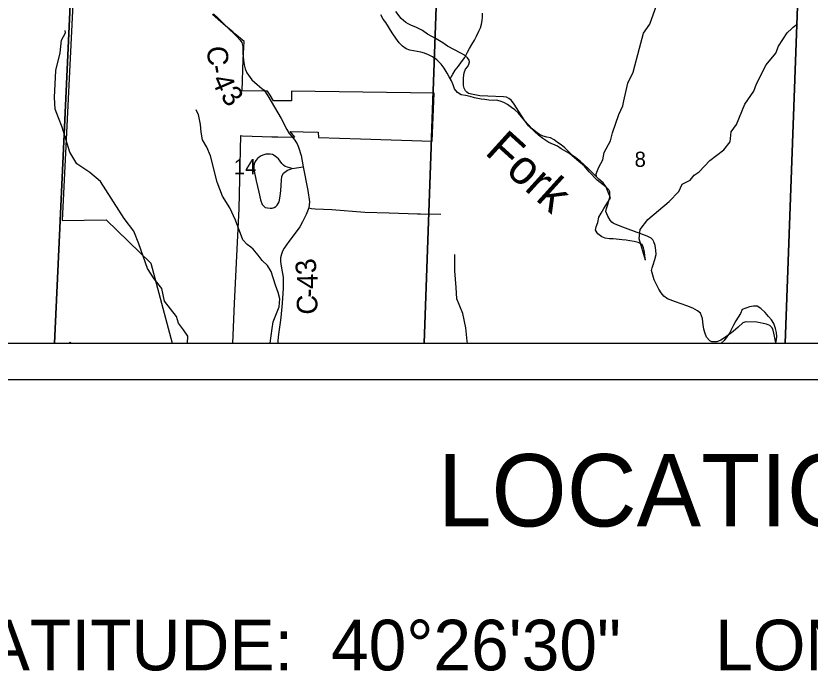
# Model space of a CAD drawing. Extents: x 0 to 34, y 0 to 22.
# Drawn here: x 3.261 to 5.456, y 13.194 to 15.005 of the extents above; entities that cross this region are included whole.
import ezdxf

# ---------------------------------------------------------------- set-up
doc = ezdxf.new("R2010")
doc.units = 0
for name, color, linetype in [('Default', 7, 'Continuous'), ('GM_X_County_Road', 7, 'Continuous'), ('GM_X_County_Road_Text', 7, 'Continuous'), ('GM_X_Minor_River', 7, 'Continuous'), ('GM_X_Minor_River_Text', 7, 'Continuous'), ('GM_X_Section_Text', 7, 'Continuous'), ('GM_X_Township_Road', 7, 'Continuous'), ('SH_Cut_Line', 7, 'Continuous'), ('SH_Data', 7, 'Continuous'), ('SH_Text', 7, 'Continuous')]:
    doc.layers.add(name, color=color, linetype=linetype)

msp = doc.modelspace()

# ---------------------------------------------------------------- linework, layer by layer
at = {"layer": 'Default'}
for p, q in [((3.3681, 14.1), (3.4148, 15.1232)), ((3.4148, 15.1232), (3.3681, 14.1)), ((3.4223, 15.1228), (3.389, 14.4392)), ((4.3897, 14.1), (4.4256, 15.1132)), ((4.4256, 15.1132), (4.3897, 14.1)), ((5.4229, 15.0756), (5.3878, 14.1)), ((5.3878, 14.1), (5.4229, 15.0756)), ((3.8279, 14.9887), (3.8044, 15.0089)), ((3.8459, 14.9733), (3.8279, 14.9887)), ((3.8516, 14.9685), (3.8459, 14.9733)), ((3.8606, 14.9607), (3.8516, 14.9685)), ((3.8664, 14.9558), (3.8606, 14.9607)), ((3.8917, 14.9341), (3.8664, 14.9558)), ((3.8897, 14.8843), (3.8917, 14.9341)), ((3.8867, 14.7981), (3.8897, 14.8843)), ((3.9476, 14.7973), (3.8867, 14.7981)), ((3.957, 14.7973), (3.9476, 14.7973)), ((3.9636, 14.7854), (3.957, 14.7973)), ((4.4177, 14.7917), (4.023, 14.7972)), ((4.023, 14.7972), (4.023, 14.77)), ((3.9727, 14.7699), (3.9636, 14.7854)), ((4.412, 14.6591), (4.4177, 14.7917)), ((4.023, 14.77), (3.9727, 14.7699)), ((3.878, 14.4728), (3.8829, 14.674)), ((3.8829, 14.674), (3.8873, 14.6738)), ((3.8873, 14.6738), (3.9684, 14.671)), ((3.9684, 14.671), (3.985, 14.6707)), ((3.985, 14.6707), (4.0317, 14.6698)), ((4.0317, 14.6698), (4.0192, 14.6857)), ((4.0192, 14.6857), (4.0552, 14.6845)), ((4.0552, 14.6845), (4.0969, 14.6836)), ((4.0969, 14.6836), (4.0972, 14.6685)), ((4.0972, 14.6685), (4.214, 14.6654)), ((4.214, 14.6654), (4.412, 14.6591)), ((3.8654, 14.21), (3.878, 14.4728)), ((3.389, 14.4392), (3.5109, 14.4412)), ((3.5109, 14.4412), (3.634, 14.3213)), ((3.634, 14.3213), (3.6931, 14.1)), ((3.8609, 14.1), (3.8654, 14.21)), ((2.1, 14.1), (6.7017, 14.1)), ((3.167, 14.1), (3.3681, 14.1)), ((3.3681, 14.1), (4.3897, 14.1)), ((3.4115, 14.1029), (3.4086, 14.1)), ((3.4086, 14.1), (3.4147, 14.1)), ((3.6931, 14.1), (3.8609, 14.1)), ((4.3897, 14.1), (5.3878, 14.1)), ((5.3878, 14.1), (6.3909, 14.1))]:
    msp.add_line(p, q, dxfattribs=at)
msp.add_arc((3.4499, 14.1421), 0.0549, 225.573, 230.0477, dxfattribs=at)
at = {"layer": 'GM_X_County_Road'}
for p, q in [((3.8069, 15.0107), (3.8205, 14.9991)), ((3.8205, 14.9991), (3.8434, 14.9758)), ((3.8434, 14.9758), (3.8711, 14.9492)), ((3.8711, 14.9492), (3.881, 14.9376)), ((3.881, 14.9376), (3.8856, 14.9312)), ((3.8856, 14.9312), (3.8877, 14.9242)), ((3.8877, 14.9242), (3.888, 14.9232)), ((3.888, 14.9232), (3.8888, 14.9019)), ((3.8888, 14.9019), (3.8901, 14.883)), ((3.8901, 14.883), (3.892, 14.8695)), ((3.892, 14.8695), (3.8949, 14.859)), ((3.8949, 14.859), (3.8993, 14.8473)), ((3.8993, 14.8473), (3.9134, 14.8281)), ((3.9134, 14.8281), (3.9276, 14.815)), ((3.9276, 14.815), (3.9413, 14.8042)), ((3.9413, 14.8042), (3.947, 14.7997)), ((3.947, 14.7997), (3.9575, 14.7844)), ((3.9575, 14.7844), (3.9762, 14.7527)), ((3.9762, 14.7527), (3.9942, 14.7211)), ((3.9942, 14.7211), (4.0103, 14.6913)), ((4.0103, 14.6913), (4.0168, 14.6798)), ((4.0168, 14.6798), (4.0186, 14.6776)), ((4.0186, 14.6776), (4.0271, 14.6671)), ((4.0271, 14.6671), (4.0324, 14.6612)), ((4.0324, 14.6612), (4.0352, 14.6571)), ((4.0352, 14.6571), (4.0386, 14.6514)), ((4.0386, 14.6514), (4.0424, 14.6423)), ((4.0424, 14.6423), (4.0495, 14.6188)), ((4.0495, 14.6188), (4.0555, 14.5876)), ((4.0555, 14.5876), (4.0678, 14.522)), ((4.0678, 14.522), (4.0728, 14.4907)), ((4.0728, 14.4907), (4.0712, 14.4745)), ((4.0712, 14.4745), (4.0635, 14.4563)), ((4.0635, 14.4563), (4.0529, 14.4353)), ((4.0529, 14.4353), (4.0455, 14.4222)), ((4.0356, 14.4077), (4.0156, 14.3812)), ((4.0455, 14.4222), (4.0356, 14.4077)), ((4.0156, 14.3812), (4.0029, 14.363)), ((4.0029, 14.363), (3.9984, 14.3544)), ((3.9929, 14.3361), (3.9928, 14.3258)), ((3.9949, 14.3463), (3.9929, 14.3361)), ((3.9984, 14.3544), (3.9949, 14.3463)), ((3.9928, 14.3258), (3.9945, 14.3132)), ((3.9945, 14.3132), (3.9995, 14.2829)), ((3.9995, 14.2829), (4.0001, 14.252)), ((4.0001, 14.252), (3.9968, 14.2106)), ((3.9968, 14.2106), (3.9933, 14.1709)), ((3.9933, 14.1709), (3.9916, 14.1579)), ((3.9916, 14.1579), (3.9872, 14.125)), ((3.9872, 14.125), (3.9849, 14.1078)), ((3.9849, 14.1078), (3.9847, 14.1))]:
    msp.add_line(p, q, dxfattribs=at)
at = {"layer": 'GM_X_Minor_River'}
for p, q in [((5.0129, 14.9819), (5.0323, 15.0369)), ((4.2766, 14.996), (4.2698, 15.008)), ((4.2838, 14.9863), (4.2766, 14.996)), ((4.5501, 14.9919), (4.5509, 15.0019)), ((4.5509, 15.0019), (4.5506, 15.0121)), ((4.2913, 14.9748), (4.2838, 14.9863)), ((4.297, 14.9651), (4.2913, 14.9748)), ((4.5407, 14.9624), (4.545, 14.9724)), ((4.545, 14.9724), (4.5477, 14.982)), ((4.5477, 14.982), (4.5501, 14.9919)), ((4.996, 14.9573), (5.0129, 14.9819)), ((5.4062, 14.9697), (5.4096, 14.9739)), ((5.4096, 14.9739), (5.4211, 14.9832)), ((3.3875, 14.9379), (3.3978, 14.9582)), ((3.3978, 14.9582), (3.3976, 14.9647)), ((4.3026, 14.955), (4.297, 14.9651)), ((4.311, 14.9431), (4.3026, 14.955)), ((4.5343, 14.9485), (4.5407, 14.9624)), ((4.9846, 14.916), (4.996, 14.9573)), ((5.3686, 14.9212), (5.3929, 14.9577)), ((5.3929, 14.9577), (5.4062, 14.9697)), ((3.3836, 14.9029), (3.3875, 14.9379)), ((4.3201, 14.9304), (4.311, 14.9431)), ((4.3299, 14.9212), (4.3201, 14.9304)), ((4.521, 14.926), (4.5286, 14.938)), ((4.5286, 14.938), (4.5343, 14.9485)), ((4.34, 14.9139), (4.3299, 14.9212)), ((4.35, 14.9104), (4.34, 14.9139)), ((4.3603, 14.9085), (4.35, 14.9104)), ((4.3707, 14.9061), (4.3603, 14.9085)), ((4.3802, 14.9049), (4.3707, 14.9061)), ((4.5091, 14.9043), (4.5149, 14.9152)), ((4.5149, 14.9152), (4.521, 14.926)), ((4.9673, 14.8496), (4.9846, 14.916)), ((5.3617, 14.9024), (5.3686, 14.9212)), ((3.3713, 14.854), (3.3836, 14.9029)), ((4.3902, 14.9018), (4.3802, 14.9049)), ((4.4017, 14.8972), (4.3902, 14.9018)), ((4.4126, 14.8915), (4.4017, 14.8972)), ((4.4242, 14.8831), (4.4126, 14.8915)), ((4.4928, 14.8776), (4.5016, 14.89)), ((4.5016, 14.89), (4.5091, 14.9043)), ((5.3351, 14.8701), (5.3617, 14.9024)), ((4.4364, 14.8713), (4.4242, 14.8831)), ((4.4447, 14.8601), (4.4364, 14.8713)), ((4.4749, 14.855), (4.4841, 14.8663)), ((4.4841, 14.8663), (4.4928, 14.8776)), ((5.308, 14.8176), (5.3351, 14.8701)), ((3.3681, 14.7795), (3.3713, 14.854)), ((4.4531, 14.8467), (4.4447, 14.8601)), ((4.4584, 14.8366), (4.4531, 14.8467)), ((4.4615, 14.8312), (4.4688, 14.8438)), ((4.4688, 14.8438), (4.4749, 14.855)), ((4.9527, 14.8186), (4.9673, 14.8496)), ((4.4648, 14.8254), (4.4584, 14.8366)), ((4.4701, 14.8141), (4.4648, 14.8254)), ((4.9414, 14.7705), (4.9527, 14.8186)), ((4.4735, 14.8036), (4.4701, 14.8141)), ((4.4818, 14.7936), (4.4735, 14.8036)), ((5.2758, 14.7612), (5.3004, 14.7973)), ((5.3004, 14.7973), (5.308, 14.8176)), ((3.3694, 14.7472), (3.3681, 14.7795)), ((4.4923, 14.7871), (4.4818, 14.7936)), ((4.5037, 14.7851), (4.4923, 14.7871)), ((4.5171, 14.7821), (4.5037, 14.7851)), ((4.5286, 14.7787), (4.5171, 14.7821)), ((4.5474, 14.7751), (4.5286, 14.7787)), ((4.5577, 14.7735), (4.5474, 14.7751)), ((4.5684, 14.7716), (4.5577, 14.7735)), ((4.5802, 14.7715), (4.5684, 14.7716)), ((4.5897, 14.7718), (4.5802, 14.7715)), ((4.6, 14.7691), (4.5897, 14.7718)), ((4.61, 14.7652), (4.6, 14.7691)), ((4.6197, 14.7602), (4.61, 14.7652)), ((4.6306, 14.7522), (4.6197, 14.7602)), ((4.9281, 14.7323), (4.9387, 14.7564)), ((4.9387, 14.7564), (4.9414, 14.7705)), ((5.253, 14.7049), (5.2758, 14.7612)), ((3.3785, 14.7234), (3.3694, 14.7472)), ((3.7611, 14.7407), (3.7591, 14.7452)), ((3.7658, 14.7324), (3.7611, 14.7407)), ((3.7712, 14.7044), (3.7658, 14.7324)), ((4.6403, 14.7453), (4.6306, 14.7522)), ((4.6505, 14.7365), (4.6403, 14.7453)), ((4.6588, 14.7261), (4.6505, 14.7365)), ((4.9098, 14.6814), (4.9281, 14.7323)), ((3.3888, 14.6977), (3.3785, 14.7234)), ((4.6679, 14.7149), (4.6588, 14.7261)), ((4.6777, 14.7038), (4.6679, 14.7149)), ((3.4101, 14.6282), (3.3888, 14.6977)), ((3.7735, 14.6835), (3.7712, 14.7044)), ((4.6883, 14.6924), (4.6777, 14.7038)), ((4.6981, 14.6847), (4.6883, 14.6924)), ((5.2386, 14.6849), (5.253, 14.7049)), ((3.7769, 14.6623), (3.7735, 14.6835)), ((4.7082, 14.6774), (4.6981, 14.6847)), ((4.7182, 14.6724), (4.7082, 14.6774)), ((4.7282, 14.6701), (4.7182, 14.6724)), ((4.7389, 14.6677), (4.7282, 14.6701)), ((4.7486, 14.6627), (4.7389, 14.6677)), ((4.9049, 14.66), (4.9098, 14.6814)), ((5.2357, 14.6571), (5.2386, 14.6849)), ((3.789, 14.6423), (3.7769, 14.6623)), ((4.7583, 14.6554), (4.7486, 14.6627)), ((4.768, 14.6489), (4.7583, 14.6554)), ((4.7786, 14.6401), (4.768, 14.6489)), ((4.8869, 14.6274), (4.9049, 14.66)), ((5.2183, 14.6348), (5.2357, 14.6571)), ((3.4292, 14.5958), (3.4101, 14.6282)), ((3.7992, 14.6182), (3.789, 14.6423)), ((4.7899, 14.629), (4.7786, 14.6401)), ((4.7994, 14.6194), (4.7899, 14.629)), ((4.8835, 14.6069), (4.8869, 14.6274)), ((5.1791, 14.6053), (5.2183, 14.6348)), ((3.8171, 14.5451), (3.7992, 14.6182)), ((4.8091, 14.6129), (4.7994, 14.6194)), ((4.8212, 14.6034), (4.8091, 14.6129)), ((4.8321, 14.5931), (4.8212, 14.6034)), ((4.8725, 14.5869), (4.8835, 14.6069)), ((5.1498, 14.5744), (5.1791, 14.6053)), ((3.4655, 14.5717), (3.4292, 14.5958)), ((4.8427, 14.5827), (4.8321, 14.5931)), ((4.8623, 14.564), (4.8427, 14.5827)), ((4.8653, 14.5682), (4.8725, 14.5869)), ((3.4947, 14.5471), (3.4655, 14.5717)), ((4.8725, 14.554), (4.8623, 14.564)), ((4.866, 14.5603), (4.8653, 14.5682)), ((5.1245, 14.5511), (5.1356, 14.5646)), ((5.1356, 14.5646), (5.1498, 14.5744)), ((3.56, 14.4448), (3.4947, 14.5471)), ((3.8318, 14.5069), (3.8171, 14.5451)), ((4.8842, 14.5433), (4.8725, 14.554)), ((4.8914, 14.5333), (4.8842, 14.5433)), ((4.8959, 14.5228), (4.8914, 14.5333)), ((5.0933, 14.5195), (5.1028, 14.5394)), ((5.1028, 14.5394), (5.1245, 14.5511)), ((4.9004, 14.513), (4.8959, 14.5228)), ((4.9042, 14.5025), (4.9004, 14.513)), ((5.067, 14.492), (5.0933, 14.5195)), ((3.8524, 14.4742), (3.8318, 14.5069)), ((4.8926, 14.4828), (4.8991, 14.4925)), ((4.8991, 14.4925), (4.9042, 14.5025)), ((5.0074, 14.442), (5.067, 14.492)), ((3.8678, 14.4402), (3.8524, 14.4742)), ((4.8785, 14.4595), (4.8861, 14.4727)), ((4.8861, 14.4727), (4.8926, 14.4828)), ((4.8698, 14.4341), (4.8728, 14.4487)), ((4.8728, 14.4487), (4.8785, 14.4595)), ((3.5867, 14.4102), (3.56, 14.4448)), ((3.8888, 14.3859), (3.8678, 14.4402)), ((4.8652, 14.4222), (4.8698, 14.4341)), ((4.9867, 14.4147), (5.0074, 14.442)), ((3.6009, 14.3747), (3.5867, 14.4102)), ((4.8629, 14.4123), (4.8652, 14.4222)), ((4.8693, 14.4026), (4.8629, 14.4123)), ((4.8805, 14.3946), (4.8693, 14.4026)), ((4.9841, 14.3892), (4.9867, 14.4147)), ((3.9, 14.3727), (3.8888, 14.3859)), ((4.8902, 14.3907), (4.8805, 14.3946)), ((4.902, 14.3891), (4.8902, 14.3907)), ((4.9119, 14.3883), (4.902, 14.3891)), ((4.9371, 14.3861), (4.9119, 14.3883)), ((4.9478, 14.3849), (4.9371, 14.3861)), ((4.9581, 14.3833), (4.9478, 14.3849)), ((4.9703, 14.3814), (4.9581, 14.3833)), ((4.9814, 14.3783), (4.9703, 14.3814)), ((5.0012, 14.3299), (4.9841, 14.3892)), ((3.6252, 14.3071), (3.6009, 14.3747)), ((3.9107, 14.3657), (3.9, 14.3727)), ((3.9172, 14.3605), (3.9107, 14.3657)), ((3.9307, 14.344), (3.9172, 14.3605)), ((4.9926, 14.3733), (4.9814, 14.3783)), ((4.9956, 14.3635), (4.9926, 14.3733)), ((4.9982, 14.3526), (4.9956, 14.3635)), ((3.942, 14.3289), (3.9307, 14.344)), ((4.4746, 14.3284), (4.4743, 14.3451)), ((4.9997, 14.3416), (4.9982, 14.3526)), ((5.0012, 14.3299), (4.9997, 14.3416)), ((3.9566, 14.3151), (3.942, 14.3289)), ((3.9667, 14.2989), (3.9566, 14.3151)), ((4.4743, 14.2999), (4.4746, 14.3284)), ((3.6435, 14.2785), (3.6252, 14.3071)), ((3.9791, 14.2604), (3.9667, 14.2989)), ((4.4778, 14.254), (4.4743, 14.2999)), ((3.6647, 14.2515), (3.6435, 14.2785)), ((3.6722, 14.2166), (3.6647, 14.2515)), ((3.9862, 14.2403), (3.9791, 14.2604)), ((4.4802, 14.2229), (4.4778, 14.254)), ((3.9907, 14.2229), (3.9862, 14.2403)), ((3.7054, 14.1739), (3.6722, 14.2166)), ((3.9892, 14.2009), (3.9907, 14.2229)), ((4.4961, 14.1824), (4.4802, 14.2229)), ((3.9718, 14.1595), (3.9892, 14.2009)), ((4.5047, 14.1431), (4.4961, 14.1824)), ((5.2636, 14.1826), (5.2571, 14.1725)), ((5.269, 14.193), (5.2636, 14.1826)), ((5.2787, 14.1971), (5.269, 14.193)), ((5.2892, 14.2005), (5.2787, 14.1971)), ((5.3002, 14.2027), (5.2892, 14.2005)), ((5.3101, 14.2023), (5.3002, 14.2027)), ((5.3205, 14.1965), (5.3101, 14.2023)), ((5.3319, 14.1855), (5.3205, 14.1965)), ((5.3414, 14.1744), (5.3319, 14.1855)), ((3.7107, 14.1557), (3.7054, 14.1739)), ((5.2513, 14.1624), (5.2448, 14.1501)), ((5.2571, 14.1725), (5.2513, 14.1624)), ((5.3497, 14.1647), (5.3414, 14.1744)), ((5.3565, 14.1543), (5.3497, 14.1647)), ((3.7246, 14.1369), (3.7107, 14.1557)), ((3.9642, 14.1), (3.9695, 14.1405)), ((3.9695, 14.1405), (3.9718, 14.1595)), ((4.508, 14.1055), (4.5047, 14.1431)), ((5.2395, 14.1389), (5.2337, 14.128)), ((5.2448, 14.1501), (5.2395, 14.1389)), ((5.3611, 14.1408), (5.3565, 14.1543)), ((5.3637, 14.1298), (5.3611, 14.1408)), ((3.7366, 14.1193), (3.7246, 14.1369)), ((3.7352, 14.1), (3.7366, 14.1193)), ((5.2265, 14.1179), (5.2188, 14.1078)), ((5.2337, 14.128), (5.2265, 14.1179)), ((5.3622, 14.1047), (5.3648, 14.1181)), ((5.3648, 14.1181), (5.3637, 14.1298)), ((4.509, 14.1), (4.508, 14.1055)), ((5.2188, 14.1078), (5.2103, 14.1)), ((5.3619, 14.1), (5.3622, 14.1047))]:
    msp.add_line(p, q, dxfattribs=at)
at = {"layer": 'GM_X_Township_Road'}
for p, q in [((4.3262, 14.9977), (4.3116, 15.0169)), ((4.3388, 14.9864), (4.3262, 14.9977)), ((4.3452, 14.9828), (4.3388, 14.9864)), ((4.3529, 14.9796), (4.3452, 14.9828)), ((4.3684, 14.9733), (4.3529, 14.9796)), ((4.3851, 14.9643), (4.3684, 14.9733)), ((4.3991, 14.9547), (4.3851, 14.9643)), ((4.4232, 14.9412), (4.3991, 14.9547)), ((4.4414, 14.9304), (4.4232, 14.9412)), ((4.4543, 14.921), (4.4414, 14.9304)), ((4.4913, 14.9019), (4.4543, 14.921)), ((4.5014, 14.8964), (4.4913, 14.9019)), ((4.5098, 14.8893), (4.5014, 14.8964)), ((4.5139, 14.8828), (4.5098, 14.8893)), ((4.5041, 14.8573), (4.5099, 14.8652)), ((4.5099, 14.8652), (4.5133, 14.8716)), ((4.5133, 14.8716), (4.5147, 14.8777)), ((4.5147, 14.8777), (4.5139, 14.8828)), ((4.4985, 14.8339), (4.4999, 14.8479)), ((4.4999, 14.8479), (4.5041, 14.8573)), ((4.4983, 14.8124), (4.4985, 14.8339)), ((4.5004, 14.805), (4.4983, 14.8124)), ((4.504, 14.798), (4.5004, 14.805)), ((4.5072, 14.7944), (4.504, 14.798)), ((4.512, 14.7909), (4.5072, 14.7944)), ((4.525, 14.7873), (4.512, 14.7909)), ((4.5434, 14.7841), (4.525, 14.7873)), ((4.5652, 14.7834), (4.5434, 14.7841)), ((4.6092, 14.781), (4.5652, 14.7834)), ((4.6168, 14.7799), (4.6092, 14.781)), ((4.6233, 14.7766), (4.6168, 14.7799)), ((4.6307, 14.7712), (4.6233, 14.7766)), ((4.6386, 14.7608), (4.6307, 14.7712)), ((4.6514, 14.7407), (4.6386, 14.7608)), ((4.6662, 14.7174), (4.6514, 14.7407)), ((4.6779, 14.7014), (4.6662, 14.7174)), ((4.6945, 14.6853), (4.6779, 14.7014)), ((4.7055, 14.6755), (4.6945, 14.6853)), ((4.7176, 14.6661), (4.7055, 14.6755)), ((4.7346, 14.6551), (4.7176, 14.6661)), ((4.7583, 14.6445), (4.7346, 14.6551)), ((4.7682, 14.6374), (4.7583, 14.6445)), ((3.9462, 14.6213), (3.9395, 14.6183)), ((3.9523, 14.6229), (3.9462, 14.6213)), ((3.9581, 14.6232), (3.9523, 14.6229)), ((3.9639, 14.6227), (3.9581, 14.6232)), ((3.9702, 14.6214), (3.9639, 14.6227)), ((3.9748, 14.6193), (3.9702, 14.6214)), ((4.7914, 14.6242), (4.7682, 14.6374)), ((4.8118, 14.6073), (4.7914, 14.6242)), ((3.9217, 14.6004), (3.9199, 14.5956)), ((3.9245, 14.6053), (3.9217, 14.6004)), ((3.9287, 14.6104), (3.9245, 14.6053)), ((3.9334, 14.6145), (3.9287, 14.6104)), ((3.9395, 14.6183), (3.9334, 14.6145)), ((3.9791, 14.6164), (3.9748, 14.6193)), ((3.9828, 14.6135), (3.9791, 14.6164)), ((3.9867, 14.6095), (3.9828, 14.6135)), ((3.9958, 14.5968), (3.9867, 14.6095)), ((4.8331, 14.5898), (4.8118, 14.6073)), ((3.9199, 14.5956), (3.9187, 14.5896)), ((3.9187, 14.5896), (3.9187, 14.5831)), ((3.9187, 14.5831), (3.9197, 14.5755)), ((4.0006, 14.5922), (3.9958, 14.5968)), ((4.0056, 14.5888), (4.0006, 14.5922)), ((4.0008, 14.5707), (4.0115, 14.5781)), ((4.0249, 14.5828), (4.0056, 14.5888)), ((4.0115, 14.5781), (4.0249, 14.5828)), ((4.0249, 14.5828), (4.0555, 14.5876)), ((4.846, 14.5744), (4.8331, 14.5898)), ((3.9197, 14.5755), (3.9255, 14.5495)), ((3.995, 14.5507), (3.9966, 14.5622)), ((3.9966, 14.5622), (4.0008, 14.5707)), ((4.8675, 14.5505), (4.846, 14.5744)), ((3.9255, 14.5495), (3.9324, 14.5175)), ((3.9933, 14.5226), (3.995, 14.5507)), ((4.8929, 14.5318), (4.8675, 14.5505)), ((3.9324, 14.5175), (3.937, 14.4966)), ((3.9915, 14.5065), (3.9933, 14.5226)), ((4.9002, 14.5245), (4.8929, 14.5318)), ((4.9026, 14.5186), (4.9002, 14.5245)), ((4.9025, 14.5053), (4.9028, 14.5124)), ((4.9028, 14.5124), (4.9026, 14.5186)), ((3.937, 14.4966), (3.942, 14.4841)), ((3.9865, 14.4861), (3.9889, 14.4914)), ((3.9889, 14.4914), (3.9915, 14.5065)), ((4.8986, 14.4867), (4.9025, 14.5053)), ((3.942, 14.4841), (3.9455, 14.4796)), ((3.9455, 14.4796), (3.9503, 14.4757)), ((3.9503, 14.4757), (3.9564, 14.474)), ((3.9564, 14.474), (3.9638, 14.4733)), ((3.9638, 14.4733), (3.9699, 14.4738)), ((3.9699, 14.4738), (3.9748, 14.4753)), ((3.9748, 14.4753), (3.9792, 14.4781)), ((3.9792, 14.4781), (3.9829, 14.4817)), ((3.9829, 14.4817), (3.9865, 14.4861)), ((4.0712, 14.4745), (4.0784, 14.4728)), ((4.0784, 14.4728), (4.0884, 14.4719)), ((4.0884, 14.4719), (4.1342, 14.4695)), ((4.1342, 14.4695), (4.2255, 14.4627)), ((4.8917, 14.4644), (4.8934, 14.4729)), ((4.8934, 14.4729), (4.8986, 14.4867)), ((4.2255, 14.4627), (4.2926, 14.4609)), ((4.2926, 14.4609), (4.3711, 14.4582)), ((4.3711, 14.4582), (4.3795, 14.4581)), ((4.3795, 14.4581), (4.4353, 14.4573)), ((4.8972, 14.4517), (4.8917, 14.4644)), ((4.9036, 14.44), (4.8972, 14.4517)), ((4.9081, 14.4352), (4.9036, 14.44)), ((4.9124, 14.432), (4.9081, 14.4352)), ((4.9175, 14.429), (4.9124, 14.432)), ((4.9385, 14.4207), (4.9175, 14.429)), ((4.9532, 14.4152), (4.9385, 14.4207)), ((5.0059, 14.3962), (4.9532, 14.4152)), ((5.0175, 14.3908), (5.0059, 14.3962)), ((5.0216, 14.3859), (5.0175, 14.3908)), ((5.0247, 14.3801), (5.0216, 14.3859)), ((5.0284, 14.3701), (5.0247, 14.3801)), ((5.0304, 14.3574), (5.0284, 14.3701)), ((5.0313, 14.3452), (5.0304, 14.3574)), ((5.0269, 14.3312), (5.0313, 14.3452)), ((5.0195, 14.3083), (5.0226, 14.3166)), ((5.0226, 14.3166), (5.0269, 14.3312)), ((5.018, 14.301), (5.0195, 14.3083)), ((5.0257, 14.2754), (5.018, 14.301)), ((5.038, 14.2499), (5.0257, 14.2754)), ((5.0443, 14.2395), (5.038, 14.2499)), ((5.0517, 14.23), (5.0443, 14.2395)), ((5.0624, 14.2226), (5.0517, 14.23)), ((5.0847, 14.215), (5.0624, 14.2226)), ((5.1152, 14.2035), (5.0847, 14.215)), ((5.1319, 14.1968), (5.1152, 14.2035)), ((5.1449, 14.1899), (5.1319, 14.1968)), ((5.153, 14.1829), (5.1449, 14.1899)), ((5.1561, 14.1758), (5.153, 14.1829)), ((5.1591, 14.1683), (5.1561, 14.1758)), ((5.1596, 14.1581), (5.1591, 14.1683)), ((5.1624, 14.1389), (5.1596, 14.1581)), ((5.1663, 14.1274), (5.1624, 14.1389)), ((5.2573, 14.1446), (5.2435, 14.1325)), ((5.27, 14.1564), (5.2573, 14.1446)), ((5.2786, 14.1595), (5.27, 14.1564)), ((5.309, 14.1585), (5.2786, 14.1595)), ((5.3357, 14.1532), (5.309, 14.1585)), ((5.3452, 14.1496), (5.3357, 14.1532)), ((5.3513, 14.1432), (5.3452, 14.1496)), ((5.3543, 14.1361), (5.3513, 14.1432)), ((5.1702, 14.1171), (5.1663, 14.1274)), ((5.1794, 14.1068), (5.1702, 14.1171)), ((5.2222, 14.1165), (5.2097, 14.109)), ((5.2435, 14.1325), (5.2222, 14.1165)), ((5.3584, 14.1197), (5.3543, 14.1361)), ((5.3611, 14.1058), (5.3584, 14.1197)), ((5.1845, 14.1045), (5.1794, 14.1068)), ((5.1896, 14.1036), (5.1845, 14.1045)), ((5.1988, 14.1043), (5.1896, 14.1036)), ((5.2097, 14.109), (5.1988, 14.1043)), ((5.3616, 14.1), (5.3611, 14.1058))]:
    msp.add_line(p, q, dxfattribs=at)
at = {"layer": 'SH_Cut_Line'}
msp.add_line((2.1, 14.1), (6.7017, 14.1), dxfattribs=at)
at = {"layer": 'SH_Data'}
for p, q in [((2.1, 14.1), (8.9, 14.1)), ((2, 14), (9, 14))]:
    msp.add_line(p, q, dxfattribs=at)

# ---------------------------------------------------------------- texts
at = {"layer": 'GM_X_County_Road_Text'}
for s, rotation, p in [('C', 272.7018, (3.7897, 14.9205)), ('-', 280.1308, (3.7928, 14.8659)), ('4', 293.1205, (3.801, 14.8295)), ('3', 310.1476, (3.8243, 14.7817)), ('3', 100.119, (4.0943, 14.296)), ('4', 90.1632, (4.0953, 14.2502)), ('-', 88.9286, (4.0949, 14.2256)), ('C', 88.6221, (4.0937, 14.1786))]:
    msp.add_text(s, height=0.0568, rotation=rotation, dxfattribs=at).set_placement(p)
at = {"layer": 'GM_X_Minor_River_Text'}
msp.add_text('Fork', height=0.09471, rotation=317.8356, dxfattribs=at).set_placement((4.5544, 14.6252))
at = {"layer": 'GM_X_Section_Text'}
for s, height, p in [('8', 0.0419, (4.9713, 14.5877)), ('14', 0.04186, (3.8634, 14.5672))]:
    msp.add_text(s, height=height, rotation=0, dxfattribs=at).set_placement(p)
at = {"layer": 'SH_Text'}
for s, height, p in [('LOCATION MAP', 0.2, (4.4269, 13.5938)), ('LATITUDE:  40°26\'30"     LONGITUDE:  -80°39\'45"', 0.14, (3.071, 13.1959))]:
    msp.add_text(s, height=height, dxfattribs=at).set_placement(p)

doc.saveas('drawing.dxf')
